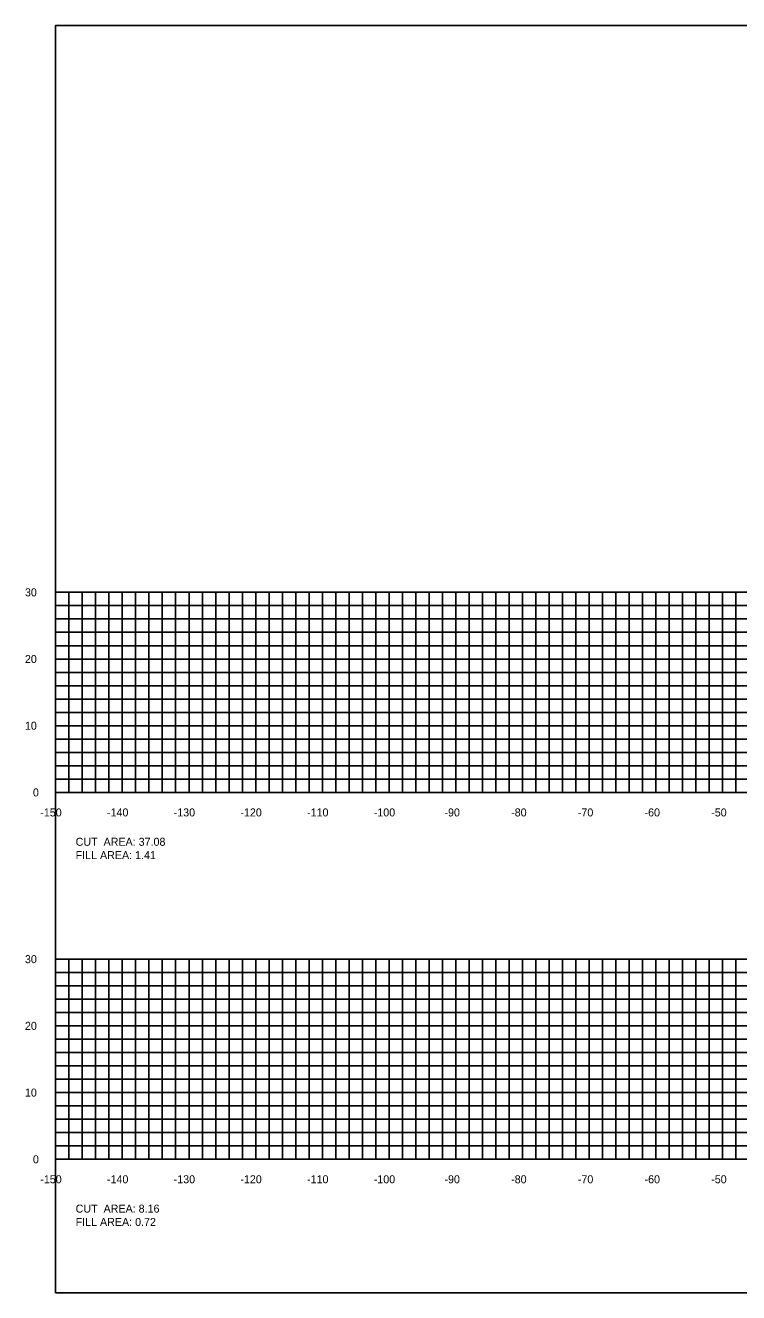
# Model space of a CAD drawing. Extents: x 1800624 to 1802445, y 250079 to 250269.
# Drawn here: x 1802136.5 to 1802243.4, y 250079.4 to 250269.4 of the extents above; entities that cross this region are included whole.
import ezdxf

# ---------------------------------------------------------------- set-up
doc = ezdxf.new("R2010")
doc.units = 0
for name, color, linetype in [('10', 7, 'Continuous'), ('31', 7, 'Continuous'), ('60', 7, 'Continuous'), ('ANNO-TXT', 7, 'Continuous'), ('Level 62', 7, 'Continuous')]:
    doc.layers.add(name, color=color, linetype=linetype)

msp = doc.modelspace()

# ---------------------------------------------------------------- linework, layer by layer
msp.add_lwpolyline([(1802141, 250079.43), (1802441, 250079.43), (1802441, 250269.43), (1802141, 250269.43)], close=True)
at = {"layer": '60'}
for p, q in [((1802140.94, 250184.43), (1802141, 250184.43)), ((1802141, 250154.43), (1802141, 250184.43)), ((1802140.94, 250174.43), (1802141, 250174.43)), ((1802140.94, 250164.43), (1802141, 250164.43)), ((1802140.94, 250154.43), (1802141, 250154.43)), ((1802141, 250154.43), (1802441, 250154.43)), ((1802141, 250154.37), (1802141, 250154.43)), ((1802151, 250154.37), (1802151, 250154.43)), ((1802161, 250154.37), (1802161, 250154.43)), ((1802171, 250154.37), (1802171, 250154.43)), ((1802181, 250154.37), (1802181, 250154.43)), ((1802191, 250154.37), (1802191, 250154.43)), ((1802201, 250154.37), (1802201, 250154.43)), ((1802211, 250154.37), (1802211, 250154.43)), ((1802221, 250154.37), (1802221, 250154.43)), ((1802231, 250154.37), (1802231, 250154.43)), ((1802241, 250154.37), (1802241, 250154.43)), ((1802140.94, 250129.43), (1802141, 250129.43)), ((1802141, 250099.43), (1802141, 250129.43)), ((1802140.94, 250119.43), (1802141, 250119.43)), ((1802140.94, 250109.43), (1802141, 250109.43)), ((1802140.94, 250099.43), (1802141, 250099.43)), ((1802141, 250099.43), (1802441, 250099.43)), ((1802141, 250099.37), (1802141, 250099.43)), ((1802151, 250099.37), (1802151, 250099.43)), ((1802161, 250099.37), (1802161, 250099.43)), ((1802171, 250099.37), (1802171, 250099.43)), ((1802181, 250099.37), (1802181, 250099.43)), ((1802191, 250099.37), (1802191, 250099.43)), ((1802201, 250099.37), (1802201, 250099.43)), ((1802211, 250099.37), (1802211, 250099.43)), ((1802221, 250099.37), (1802221, 250099.43)), ((1802231, 250099.37), (1802231, 250099.43)), ((1802241, 250099.37), (1802241, 250099.43))]:
    msp.add_line(p, q, dxfattribs=at)
at = {"layer": 'Level 62'}
for p, q in [((1802141, 250184.43), (1802441, 250184.43)), ((1802141, 250154.43), (1802141, 250184.43)), ((1802143, 250154.43), (1802143, 250184.43)), ((1802145, 250154.43), (1802145, 250184.43)), ((1802147, 250154.43), (1802147, 250184.43)), ((1802149, 250154.43), (1802149, 250184.43)), ((1802151, 250154.43), (1802151, 250184.43)), ((1802153, 250154.43), (1802153, 250184.43)), ((1802155, 250154.43), (1802155, 250184.43)), ((1802157, 250154.43), (1802157, 250184.43)), ((1802159, 250154.43), (1802159, 250184.43)), ((1802161, 250154.43), (1802161, 250184.43)), ((1802163, 250154.43), (1802163, 250184.43)), ((1802165, 250154.43), (1802165, 250184.43)), ((1802167, 250154.43), (1802167, 250184.43)), ((1802169, 250154.43), (1802169, 250184.43)), ((1802171, 250154.43), (1802171, 250184.43)), ((1802173, 250154.43), (1802173, 250184.43)), ((1802175, 250154.43), (1802175, 250184.43)), ((1802177, 250154.43), (1802177, 250184.43)), ((1802179, 250154.43), (1802179, 250184.43)), ((1802181, 250154.43), (1802181, 250184.43)), ((1802183, 250154.43), (1802183, 250184.43)), ((1802185, 250154.43), (1802185, 250184.43)), ((1802187, 250154.43), (1802187, 250184.43)), ((1802189, 250154.43), (1802189, 250184.43)), ((1802191, 250154.43), (1802191, 250184.43)), ((1802193, 250154.43), (1802193, 250184.43)), ((1802195, 250154.43), (1802195, 250184.43)), ((1802197, 250154.43), (1802197, 250184.43)), ((1802199, 250154.43), (1802199, 250184.43)), ((1802201, 250154.43), (1802201, 250184.43)), ((1802203, 250154.43), (1802203, 250184.43)), ((1802205, 250154.43), (1802205, 250184.43)), ((1802207, 250154.43), (1802207, 250184.43)), ((1802209, 250154.43), (1802209, 250184.43)), ((1802211, 250154.43), (1802211, 250184.43)), ((1802213, 250154.43), (1802213, 250184.43)), ((1802215, 250154.43), (1802215, 250184.43)), ((1802217, 250154.43), (1802217, 250184.43)), ((1802219, 250154.43), (1802219, 250184.43)), ((1802221, 250154.43), (1802221, 250184.43)), ((1802223, 250154.43), (1802223, 250184.43)), ((1802225, 250154.43), (1802225, 250184.43)), ((1802227, 250154.43), (1802227, 250184.43)), ((1802229, 250154.43), (1802229, 250184.43)), ((1802231, 250154.43), (1802231, 250184.43)), ((1802233, 250154.43), (1802233, 250184.43)), ((1802235, 250154.43), (1802235, 250184.43)), ((1802237, 250154.43), (1802237, 250184.43)), ((1802239, 250154.43), (1802239, 250184.43)), ((1802241, 250154.43), (1802241, 250184.43)), ((1802243, 250154.43), (1802243, 250184.43)), ((1802141, 250182.43), (1802441, 250182.43)), ((1802141, 250180.43), (1802441, 250180.43)), ((1802141, 250178.43), (1802441, 250178.43)), ((1802141, 250176.43), (1802441, 250176.43)), ((1802141, 250174.43), (1802441, 250174.43)), ((1802141, 250172.43), (1802441, 250172.43)), ((1802141, 250170.43), (1802441, 250170.43)), ((1802141, 250168.43), (1802441, 250168.43)), ((1802141, 250166.43), (1802441, 250166.43)), ((1802141, 250164.43), (1802441, 250164.43)), ((1802141, 250162.43), (1802441, 250162.43)), ((1802141, 250160.43), (1802441, 250160.43)), ((1802141, 250158.43), (1802441, 250158.43)), ((1802141, 250156.43), (1802441, 250156.43)), ((1802141, 250154.43), (1802441, 250154.43)), ((1802141, 250129.43), (1802441, 250129.43)), ((1802141, 250099.43), (1802141, 250129.43)), ((1802143, 250099.43), (1802143, 250129.43)), ((1802145, 250099.43), (1802145, 250129.43)), ((1802147, 250099.43), (1802147, 250129.43)), ((1802149, 250099.43), (1802149, 250129.43)), ((1802151, 250099.43), (1802151, 250129.43)), ((1802153, 250099.43), (1802153, 250129.43)), ((1802155, 250099.43), (1802155, 250129.43)), ((1802157, 250099.43), (1802157, 250129.43)), ((1802159, 250099.43), (1802159, 250129.43)), ((1802161, 250099.43), (1802161, 250129.43)), ((1802163, 250099.43), (1802163, 250129.43)), ((1802165, 250099.43), (1802165, 250129.43)), ((1802167, 250099.43), (1802167, 250129.43)), ((1802169, 250099.43), (1802169, 250129.43)), ((1802171, 250099.43), (1802171, 250129.43)), ((1802173, 250099.43), (1802173, 250129.43)), ((1802175, 250099.43), (1802175, 250129.43)), ((1802177, 250099.43), (1802177, 250129.43)), ((1802179, 250099.43), (1802179, 250129.43)), ((1802181, 250099.43), (1802181, 250129.43)), ((1802183, 250099.43), (1802183, 250129.43)), ((1802185, 250099.43), (1802185, 250129.43)), ((1802187, 250099.43), (1802187, 250129.43)), ((1802189, 250099.43), (1802189, 250129.43)), ((1802191, 250099.43), (1802191, 250129.43)), ((1802193, 250099.43), (1802193, 250129.43)), ((1802195, 250099.43), (1802195, 250129.43)), ((1802197, 250099.43), (1802197, 250129.43)), ((1802199, 250099.43), (1802199, 250129.43)), ((1802201, 250099.43), (1802201, 250129.43)), ((1802203, 250099.43), (1802203, 250129.43)), ((1802205, 250099.43), (1802205, 250129.43)), ((1802207, 250099.43), (1802207, 250129.43)), ((1802209, 250099.43), (1802209, 250129.43)), ((1802211, 250099.43), (1802211, 250129.43)), ((1802213, 250099.43), (1802213, 250129.43)), ((1802215, 250099.43), (1802215, 250129.43)), ((1802217, 250099.43), (1802217, 250129.43)), ((1802219, 250099.43), (1802219, 250129.43)), ((1802221, 250099.43), (1802221, 250129.43)), ((1802223, 250099.43), (1802223, 250129.43)), ((1802225, 250099.43), (1802225, 250129.43)), ((1802227, 250099.43), (1802227, 250129.43)), ((1802229, 250099.43), (1802229, 250129.43)), ((1802231, 250099.43), (1802231, 250129.43)), ((1802233, 250099.43), (1802233, 250129.43)), ((1802235, 250099.43), (1802235, 250129.43)), ((1802237, 250099.43), (1802237, 250129.43)), ((1802239, 250099.43), (1802239, 250129.43)), ((1802241, 250099.43), (1802241, 250129.43)), ((1802243, 250099.43), (1802243, 250129.43)), ((1802141, 250127.43), (1802441, 250127.43)), ((1802141, 250125.43), (1802441, 250125.43)), ((1802141, 250123.43), (1802441, 250123.43)), ((1802141, 250121.43), (1802441, 250121.43)), ((1802141, 250119.43), (1802441, 250119.43)), ((1802141, 250117.43), (1802441, 250117.43)), ((1802141, 250115.43), (1802441, 250115.43)), ((1802141, 250113.43), (1802441, 250113.43)), ((1802141, 250111.43), (1802441, 250111.43)), ((1802141, 250109.43), (1802441, 250109.43)), ((1802141, 250107.43), (1802441, 250107.43)), ((1802141, 250105.43), (1802441, 250105.43)), ((1802141, 250103.43), (1802441, 250103.43)), ((1802141, 250101.43), (1802441, 250101.43)), ((1802141, 250099.43), (1802441, 250099.43))]:
    msp.add_line(p, q, dxfattribs=at)

# ---------------------------------------------------------------- texts
at = {"layer": '10'}
for s, p in [('-150', (1802138.7, 250150.83)), ('-140', (1802148.7, 250150.83)), ('-130', (1802158.7, 250150.83)), ('-120', (1802168.7, 250150.83)), ('-110', (1802178.7, 250150.83)), ('-100', (1802188.7, 250150.83)), ('-90', (1802199.3, 250150.83)), ('-80', (1802209.3, 250150.83)), ('-70', (1802219.3, 250150.83)), ('-60', (1802229.3, 250150.83)), ('-50', (1802239.3, 250150.83)), ('-150', (1802138.7, 250095.83)), ('-140', (1802148.7, 250095.83)), ('-130', (1802158.7, 250095.83)), ('-120', (1802168.7, 250095.83)), ('-110', (1802178.7, 250095.83)), ('-100', (1802188.7, 250095.83)), ('-90', (1802199.3, 250095.83)), ('-80', (1802209.3, 250095.83)), ('-70', (1802219.3, 250095.83)), ('-60', (1802229.3, 250095.83)), ('-50', (1802239.3, 250095.83))]:
    msp.add_text(s, height=1.2, dxfattribs=at).set_placement(p)
at = {"layer": '31'}
for s, p in [('30', (1802136.4, 250183.83)), ('20', (1802136.4, 250173.83)), ('10', (1802136.4, 250163.83)), ('0', (1802137.6, 250153.83)), ('30', (1802136.4, 250128.83)), ('20', (1802136.4, 250118.83)), ('10', (1802136.4, 250108.83)), ('0', (1802137.6, 250098.83))]:
    msp.add_text(s, height=1.2, dxfattribs=at).set_placement(p)
at = {"layer": '60'}
for p in [(1802141, 250154.43), (1802141, 250099.43)]:
    msp.add_text('-', height=0.0001, dxfattribs=at).set_placement(p)
at = {"layer": 'ANNO-TXT'}
for s, p in [('CUT  AREA: 37.08', (1802144, 250146.43)), ('FILL AREA: 1.41', (1802144, 250144.43)), ('CUT  AREA: 8.16', (1802144, 250091.43)), ('FILL AREA: 0.72', (1802144, 250089.43))]:
    msp.add_text(s, height=1.2, dxfattribs=at).set_placement(p)

doc.saveas('drawing.dxf')
